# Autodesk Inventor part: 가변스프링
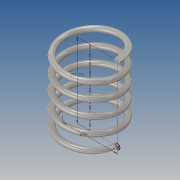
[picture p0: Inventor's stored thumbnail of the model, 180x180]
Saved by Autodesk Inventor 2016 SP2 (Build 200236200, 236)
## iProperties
Created: 2019-03
Part Number: 가변스프링
Material: 스테인레스 스틸
Document SubType Name: Modeling
Designer: EZ
Density: 8 g/cm^3
Appearance: 반연마
Mass: 62.188 g
Surface Area: 78.8368 cm^2
Volume: 7.7735 cm^3
Author: EZ
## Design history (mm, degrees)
sketch "스케치1"
  geometry: L1 (0, 0)-(20, 0); L2 (20, 0)-(20, 55.252); L3 (20, 55.252)-(0, 55.252); L4 (0, 55.252)-(0, 0); C1 r 2 at (20, 0)
  constraints: 8 end point, 2 parallel, 1 centre point, 1 coincident, 1 horizontal, 1 perpendicular
  dimensions: "d0" = 4 diameter of C1; "d2" = 40 diameter of L2 L4; "d3" = 55.25229 distance between parallel lines of L1 L3 (derived)
feature "코일1" sketch "스케치1" pitch "d4" = 10; turns "d6" = 5; dims "d5" = 55.24993 (computed from d3), "d7" = 0, angle "d8" = 90 deg, angle "d9" = 90 deg, "d10" = 0, "d11" = 0
sketch "스케치2"
  geometry: L1 (-18, 0)-(-22, 0) reference
  constraints: 1 horizontal alignment
extrude "돌출1" cut sketch "스케치2" stored distance "d12" = 10; taper "d13" = 0 deg
node "작업 평면1"
sketch "스케치3"
  geometry: L1 (-2, 0)-(2, 0) reference
  constraints: 1 horizontal alignment
extrude "돌출2" cut sketch "스케치3" stored distance "d14" = 10; taper "d15" = 0 deg
node "솔리드1"
node "절단 모서리 투영1"
node "절단 모서리 투영2"
